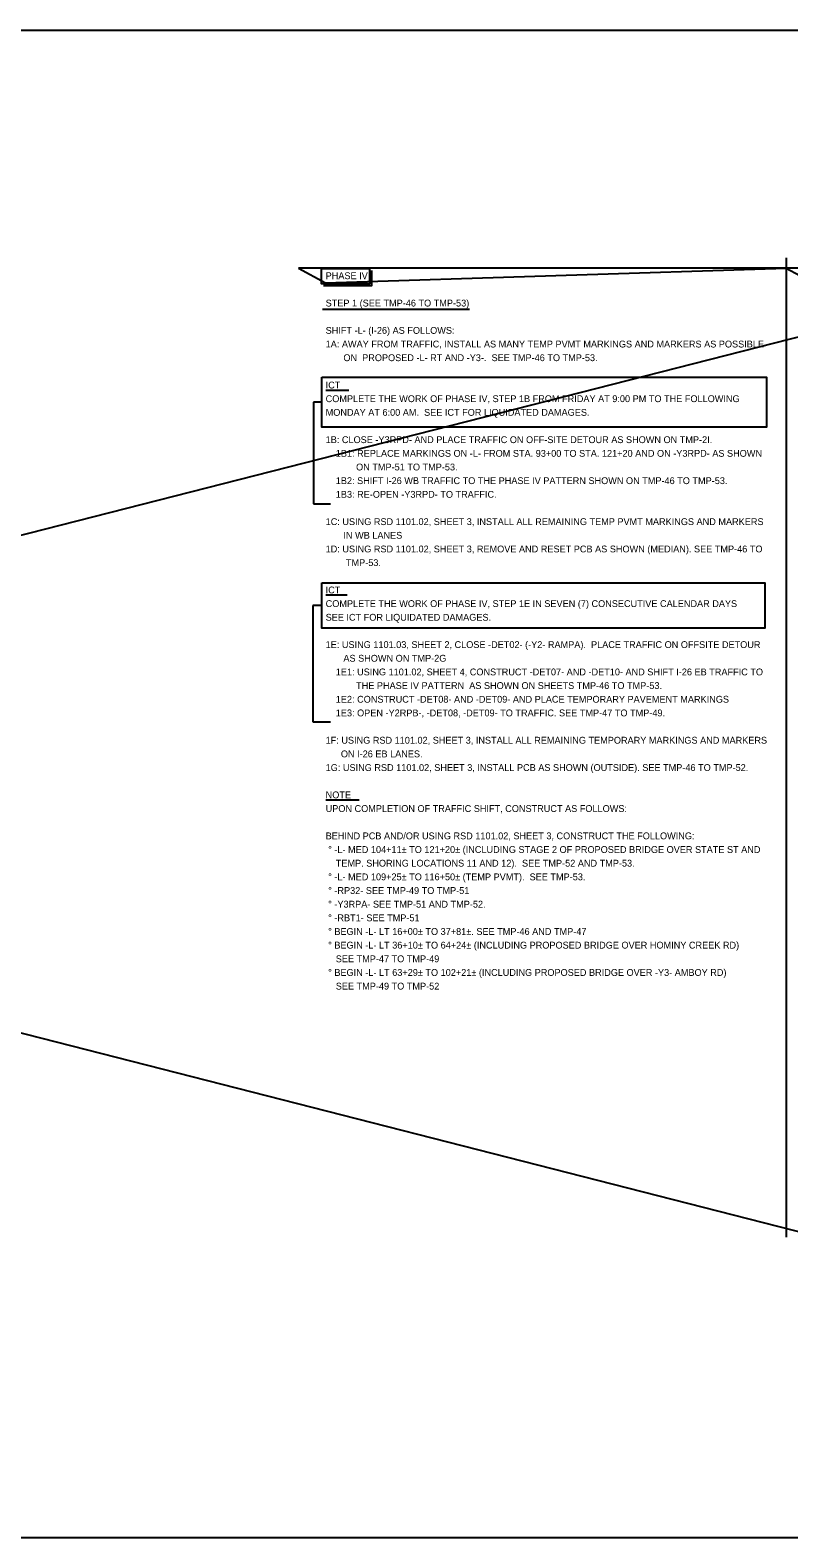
# Model space of a CAD drawing. Extents: x 2483905 to 2494512, y 366160 to 372330.
# Drawn here: x 2490737 to 2491514, y 368441 to 369986 of the extents above; entities that cross this region are included whole.
import ezdxf

# ---------------------------------------------------------------- set-up
doc = ezdxf.new("R2010")
doc.units = 0
for name, color, linetype in [('Scratch_Level_4', 7, 'Continuous'), ('Scratch_Level_6', 7, 'Continuous'), ('TC SHEET BORDER LINE THIN', 7, 'Continuous')]:
    doc.layers.add(name, color=color, linetype=linetype)

msp = doc.modelspace()

# ---------------------------------------------------------------- linework, layer by layer
at = {"layer": 'Scratch_Level_4'}
for p, q in [((2486701.2, 368441.1), (2492754.6, 369986.2)), ((2486701.2, 369986.2), (2492754.6, 368441.1))]:
    msp.add_line(p, q, dxfattribs=at)
msp.add_lwpolyline([(2486701.2, 369986.2), (2492754.6, 369986.2), (2492754.6, 368441.1), (2486701.2, 368441.1)], close=True, dxfattribs=at)
at = {"layer": 'Scratch_Level_6'}
msp.add_lwpolyline([(2491011.6, 369742.3), (2491039.5, 369727.3), (2491511.6, 369742.3), (2491539.5, 369727.3), (2492011.6, 369742.3), (2492039.5, 369727.3)], dxfattribs=at)
at = {"layer": 'TC SHEET BORDER LINE THIN'}
for p, q in [((2491511.6, 369753), (2491511.6, 368749.2)), ((2492511.6, 369742.3), (2491011.6, 369742.3)), ((2491036.4, 369700.4), (2491187.1, 369700.4)), ((2491039.8, 369617.3), (2491063.2, 369617.3)), ((2491035.5, 369605), (2491027, 369605)), ((2491027, 369605), (2491027, 369605)), ((2491027, 369605), (2491027, 369500.7)), ((2491027, 369500.7), (2491027, 369500.7)), ((2491027, 369500.7), (2491044.4, 369500.7)), ((2491035.6, 369396.7), (2491026.2, 369396.7)), ((2491026.2, 369396.7), (2491026.2, 369277.4)), ((2491039.6, 369407.4), (2491061.7, 369407.4)), ((2491026.2, 369291.8), (2491026.2, 369291.8)), ((2491026.2, 369277.4), (2491044.5, 369277.4)), ((2491039.6, 369197.6), (2491073.7, 369197.6))]:
    msp.add_line(p, q, dxfattribs=at)
for points in [[(2491035.4, 369741.9), (2491084.4, 369741.9), (2491084.4, 369726.3), (2491035.4, 369726.3)], [(2491035.5, 369630.5), (2491491.4, 369630.5), (2491491.4, 369579.4), (2491035.5, 369579.4)], [(2491035.6, 369419.7), (2491489.8, 369419.7), (2491489.8, 369373.3), (2491035.6, 369373.3)]]:
    msp.add_lwpolyline(points, close=True, dxfattribs=at)
msp.add_lwpolyline([(2491086.4, 369739.9), (2491086.4, 369724.3), (2491037.4, 369724.3)], dxfattribs=at)

# ---------------------------------------------------------------- texts
for s, p in [('PHASE IV', (2491039.5, 369731)), ('STEP 1 (SEE TMP-46 TO TMP-53)', (2491039.5, 369703)), ('SHIFT -L- (I-26) AS FOLLOWS:', (2491039.5, 369675)), ('1A: AWAY FROM TRAFFIC, INSTALL AS MANY TEMP PVMT MARKINGS AND MARKERS AS POSSIBLE', (2491039.5, 369661)), ('       ON  PROPOSED -L- RT AND -Y3-.  SEE TMP-46 TO TMP-53.', (2491039.5, 369647)), ('COMPLETE THE WORK OF PHASE IV, STEP 1B FROM FRIDAY AT 9:00 PM TO THE FOLLOWING', (2491039.5, 369605)), ('ICT', (2491039.5, 369619)), ('MONDAY AT 6:00 AM.  SEE ICT FOR LIQUIDATED DAMAGES.', (2491039.5, 369591)), ('1B: CLOSE -Y3RPD- AND PLACE TRAFFIC ON OFF-SITE DETOUR AS SHOWN ON TMP-2I.', (2491039.5, 369563)), ('    1B1: REPLACE MARKINGS ON -L- FROM STA. 93+00 TO STA. 121+20 AND ON -Y3RPD- AS SHOWN', (2491039.5, 369549)), ('            ON TMP-51 TO TMP-53.', (2491039.5, 369535)), ('    1B2: SHIFT I-26 WB TRAFFIC TO THE PHASE IV PATTERN SHOWN ON TMP-46 TO TMP-53.', (2491039.5, 369521)), ('    1B3: RE-OPEN -Y3RPD- TO TRAFFIC.', (2491039.5, 369507)), ('1C: USING RSD 1101.02, SHEET 3, INSTALL ALL REMAINING TEMP PVMT MARKINGS AND MARKERS', (2491039.5, 369479)), ('1D: USING RSD 1101.02, SHEET 3, REMOVE AND RESET PCB AS SHOWN (MEDIAN). SEE TMP-46 TO', (2491039.5, 369451)), ('       IN WB LANES', (2491039.5, 369465)), ('        TMP-53.', (2491039.5, 369437)), ('ICT', (2491039.5, 369409)), ('COMPLETE THE WORK OF PHASE IV, STEP 1E IN SEVEN (7) CONSECUTIVE CALENDAR DAYS', (2491039.5, 369395)), ('SEE ICT FOR LIQUIDATED DAMAGES.', (2491039.5, 369381)), ('1E: USING 1101.03, SHEET 2, CLOSE -DET02- (-Y2- RAMPA).  PLACE TRAFFIC ON OFFSITE DETOUR', (2491039.5, 369353)), ('       AS SHOWN ON TMP-2G', (2491039.5, 369339)), ('    1E1: USING 1101.02, SHEET 4, CONSTRUCT -DET07- AND -DET10- AND SHIFT I-26 EB TRAFFIC TO', (2491039.5, 369325)), ('    1E2: CONSTRUCT -DET08- AND -DET09- AND PLACE TEMPORARY PAVEMENT MARKINGS', (2491039.5, 369297)), ('            THE PHASE IV PATTERN  AS SHOWN ON SHEETS TMP-46 TO TMP-53.', (2491039.5, 369311)), ('    1E3: OPEN -Y2RPB-, -DET08, -DET09- TO TRAFFIC. SEE TMP-47 TO TMP-49.', (2491039.5, 369283)), ('1F: USING RSD 1101.02, SHEET 3, INSTALL ALL REMAINING TEMPORARY MARKINGS AND MARKERS', (2491039.5, 369255)), ('      ON I-26 EB LANES.', (2491039.5, 369241)), ('1G: USING RSD 1101.02, SHEET 3, INSTALL PCB AS SHOWN (OUTSIDE). SEE TMP-46 TO TMP-52.', (2491039.5, 369227)), ('NOTE', (2491039.5, 369199)), ('UPON COMPLETION OF TRAFFIC SHIFT, CONSTRUCT AS FOLLOWS:', (2491039.5, 369185)), ('BEHIND PCB AND/OR USING RSD 1101.02, SHEET 3, CONSTRUCT THE FOLLOWING:', (2491039.5, 369157)), (' ° -L- MED 104+11± TO 121+20± (INCLUDING STAGE 2 OF PROPOSED BRIDGE OVER STATE ST AND', (2491039.5, 369143)), ('    TEMP. SHORING LOCATIONS 11 AND 12).  SEE TMP-52 AND TMP-53.', (2491039.5, 369129)), (' ° -L- MED 109+25± TO 116+50± (TEMP PVMT).  SEE TMP-53.', (2491039.5, 369115)), (' ° -RP32- SEE TMP-49 TO TMP-51', (2491039.5, 369101)), (' ° -Y3RPA- SEE TMP-51 AND TMP-52. ', (2491039.5, 369087)), (' ° -RBT1- SEE TMP-51', (2491039.5, 369073)), (' ° BEGIN -L- LT 16+00± TO 37+81±. SEE TMP-46 AND TMP-47', (2491039.5, 369059)), (' ° BEGIN -L- LT 36+10± TO 64+24± (INCLUDING PROPOSED BRIDGE OVER HOMINY CREEK RD)', (2491039.5, 369045)), ('    SEE TMP-47 TO TMP-49', (2491039.5, 369031)), (' ° BEGIN -L- LT 63+29± TO 102+21± (INCLUDING PROPOSED BRIDGE OVER -Y3- AMBOY RD)', (2491039.5, 369017)), ('    SEE TMP-49 TO TMP-52', (2491039.5, 369003))]:
    msp.add_text(s, height=7, dxfattribs=at).set_placement(p)

doc.saveas('drawing.dxf')
